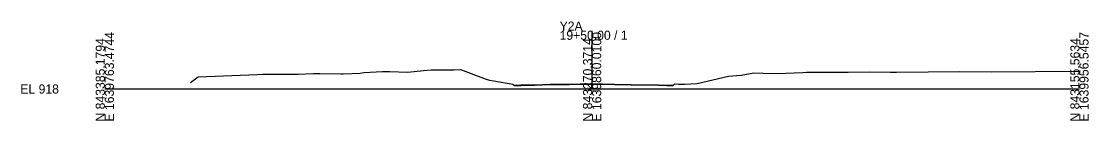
# Model space of a CAD drawing. Extents: x -26 to 303, y -10 to 10517.
# Drawn here: x -25.7 to 302.8, y 8990.3 to 9020.7 of the extents above; entities that cross this region are included whole.
import ezdxf

# ---------------------------------------------------------------- set-up
doc = ezdxf.new("R2010")
doc.units = 0
for name, color, linetype in [('Exist Cross Section Cell', 7, 'Continuous'), ('Exist XS Center Line Elevation Label', 7, 'Continuous'), ('Exist XS Ground Line', 7, 'Continuous'), ('Prop CMT Pvmt Surface Overlay', 7, 'Continuous')]:
    doc.layers.add(name, color=color, linetype=linetype)

msp = doc.modelspace()

# ---------------------------------------------------------------- linework, layer by layer
at = {"layer": 'Exist Cross Section Cell'}
for p, q in [((150, 9000), (150, 9017.89)), ((0, 9000), (150, 9000)), ((150, 9000), (300, 9000))]:
    msp.add_line(p, q, dxfattribs=at)
at = {"layer": 'Exist XS Ground Line'}
msp.add_lwpolyline([(26.4, 9001.94), (28.75, 9003.68), (46.87, 9004.49), (48.49, 9004.52), (50.05, 9004.55), (57.84, 9004.53), (59.55, 9004.52), (64.24, 9004.76), (65.79, 9004.78), (66.16, 9004.75), (72.68, 9004.66), (73.35, 9004.68), (78.64, 9004.88), (79.76, 9005.04), (85.51, 9005.39), (87.66, 9005.4), (93.29, 9005.21), (98.12, 9005.67), (100.44, 9005.83), (107.42, 9005.9), (109.46, 9005.96), (117.36, 9003.01), (118.46, 9002.7), (119.78, 9002.47), (125.58, 9001.52), (126.08, 9001.02), (127.2, 9001.07), (128.04, 9001.1), (132.3, 9001.19), (137.11, 9001.36), (142.96, 9001.39), (149.64, 9001.52), (150, 9001.51), (156.84, 9001.34), (162.04, 9001.27), (170.39, 9001.16), (172.98, 9001.1), (173.49, 9001.08), (174.93, 9001.05), (175.43, 9001.55), (176.56, 9001.52), (178.39, 9001.47), (182.3, 9001.72), (192.02, 9003.94), (195.84, 9004.23), (199.81, 9004.97), (202.65, 9004.88), (206.91, 9004.74), (214.9, 9005.09), (216.02, 9005.12), (223.07, 9005.15), (227.51, 9005.16), (228.2, 9005.17), (228.78, 9005.18), (235.3, 9005.24), (241.85, 9005.2), (242.4, 9005.2), (243.01, 9005.2), (243.66, 9005.2), (263.15, 9005.36), (272.84, 9005.25), (300, 9005.49)], dxfattribs=at)
at = {"layer": 'Prop CMT Pvmt Surface Overlay'}
msp.add_lwpolyline([(125.96, 9001.13), (127.19, 9001.2), (128.04, 9001.23), (132.3, 9001.31), (137.11, 9001.49), (142.96, 9001.52), (149.64, 9001.64), (156.84, 9001.47), (162.04, 9001.39), (170.39, 9001.29), (172.98, 9001.22), (173.5, 9001.21), (175.06, 9001.18)], dxfattribs=at)

# ---------------------------------------------------------------- texts
at = {"layer": 'Exist Cross Section Cell'}
for s, p in [('Y2A', (140, 9017.89)), ('19+50.00 / 1', (140, 9015.09)), ('EL 918', (-26, 8998.6))]:
    msp.add_text(s, height=2.8, dxfattribs=at).set_placement(p)
for s, p in [('N 843385.1794', (0, 8990)), ('E 1639763.4744', (2.8, 8990)), ('N 843270.3714', (150, 8990)), ('E 1639860.0100', (152.8, 8990)), ('N 843155.5634', (300, 8990)), ('E 1639956.5457', (302.8, 8990))]:
    msp.add_text(s, height=2.8, rotation=90, dxfattribs=at).set_placement(p)
at = {"layer": 'Exist XS Center Line Elevation Label'}
msp.add_text('919.51', height=1, dxfattribs=at).set_placement((148.24, 8999.41))

doc.saveas('drawing.dxf')
